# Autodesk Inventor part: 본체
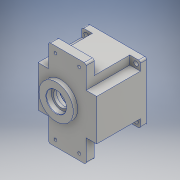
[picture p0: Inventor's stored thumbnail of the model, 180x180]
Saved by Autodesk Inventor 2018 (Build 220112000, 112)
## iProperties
Created: 2020-07
Part Number: 본체
Material: 알루미늄 6061
Document SubType Name: Modeling
Designer: Admin
Density: 2.7 g/cm^3
Appearance: 알루미늄 - 평지
Mass: 876.465 g
Surface Area: 793.597 cm^2
Volume: 324.617 cm^3
Author: Admin
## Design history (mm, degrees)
sketch "스케치1"
  geometry: L1 (-30, 70)-(30, 70); L2 (30, 70)-(30, -70); L3 (30, -70)-(-30, -70); L4 (-30, -70)-(-30, 70); L5 (-30, 70)-(30, -70); L6 (30, 70)-(-30, -70); 1 further point
  constraints: 12 end point, 2 midpoint, 2 parallel, 1 horizontal, 1 perpendicular
  dimensions: "d0" = 140 distance of L1.end L2.end; "d1" = 60 distance between parallel lines of L4 L2
extrude "돌출1" new body sketch "스케치1" distance "d2" = 13; taper "d3" = 0 deg
sketch "스케치2"
  geometry: L1 (-47, 47)-(47, 47); L2 (47, 47)-(47, -47); L3 (47, -47)-(-47, -47); L4 (-47, -47)-(-47, 47); L5 (-47, 47)-(47, -47); L6 (47, 47)-(-47, -47); 1 further point
  constraints: 12 end point, 2 midpoint, 2 parallel, 1 horizontal, 1 perpendicular
  dimensions: "d4" = 94 distance of L1.end L2.end; "d5" = 94 distance of L2.end L3.end
extrude "돌출2" join sketch "스케치2" distance "d6" = 80; taper "d7" = 0 deg
sketch "스케치3"
  geometry: L1 (-30, 33)-(30, 33); L2 (30, 33)-(30, -33); L3 (30, -33)-(-30, -33); L4 (-30, -33)-(-30, 33); L5 (-30, 33)-(30, -33); L6 (30, 33)-(-30, -33); L7 (47, 47)-(47, -47) reference; L8 (30, -33)-(47, -33); L9 (47, -33)-(47, -47); L10 (47, -47)-(30, -47); L11 (30, -47)-(30, -33); L12 (30, 33)-(47, 33); L13 (47, 33)-(47, 47); L14 (47, 47)-(30, 47); L15 (30, 47)-(30, 33); L16 (-47, 47)-(-30, 47) reference; L17 (-30, 33)-(-47, 33); L18 (-47, 33)-(-47, 47); L19 (-47, 47)-(-30, 47); L20 (-30, 47)-(-30, 33); L21 (-47, -47)-(-47, 47) reference; L22 (-30, -33)-(-47, -33); L23 (-47, -33)-(-47, -47); L24 (-47, -47)-(-30, -47); L25 (-30, -47)-(-30, -33); 1 further point
  constraints: 44 end point, 10 parallel, 5 horizontal, 5 perpendicular, 2 midpoint
  dimensions: "d8" = 66 distance of L1.end L2.end; "d9" = 60 distance of L2.end L3.end
extrude "돌출3" cut sketch "스케치3" distance "d10" = 70; taper "d11" = 0 deg
sketch "스케치4"
  geometry: C1 r 43 at (0, 0); 1 further point
  constraints: 1 centre point, 1 coincident
  dimensions: "d12" = 86 diameter of C1
extrude "돌출4" cut sketch "스케치4" distance "d13" = 9; taper "d14" = 0 deg
sketch "스케치5"
  geometry: C1 r 40 at (0, 0); 1 further point
  constraints: 1 centre point, 1 coincident
  dimensions: "d15" = 80 diameter of C1
extrude "돌출5" cut sketch "스케치5" distance "d16" = 62; taper "d17" = 0 deg
sketch "스케치6"
  geometry: L1 (0, -40)-(0, 40); L2 (-40, 0)-(40, 0); L3 (-11, -40)-(-11, 40); L4 (20, -40)-(20, 40); A1 r 40 centre (0, 0) between (0, -40) and (0, 40) reference; A2 r 21 centre (-11, 0) between (6.119, 12.163) and (6.119, -12.163); A3 r 15 centre (20, 0) between (10.47, -11.584) and (10.47, 11.584); A4 r 3 centre (8.565, -13.901) between (10.47, -11.584) and (6.119, -12.163); A5 r 3 centre (8.565, 13.901) between (6.119, 12.163) and (10.47, 11.584); 3 further points
  constraints: 12 point on circle, 8 end point, 6 midpoint, 4 centre point, 3 symmetric about line, 2 parallel, 2 point on line, 2 tangent, 1 horizontal, 1 vertical, 1 other
  dimensions: "d18" = 11 distance between parallel lines of L1 L3; "d19" = 20 distance between parallel lines of L1 L4; "d20" = 42 diameter of A2; "d21" = 30 diameter of A3; "d22" = 6 diameter of A4
extrude "돌출6" join sketch "스케치6" distance "d23" = 7; taper "d24" = 0 deg
sketch "스케치7"
  geometry: C1 r 17.5 at (-11, 0); A1 r 21 centre (-11, 0) between (6.119, 12.163) and (6.119, -12.163) reference; 1 further point
  constraints: 1 centre point, 1 coincident
  dimensions: "d25" = 35 diameter of C1
extrude "돌출7" cut sketch "스케치7" distance "d26" = 10; taper "d27" = 0 deg
sketch "스케치8"
  geometry: C1 r 27.5 at (-11, 0); A1 r 21 centre (-11, 0) between (6.119, 12.163) and (6.119, -12.163) reference; 1 further point
  constraints: 1 centre point, 1 coincident
  dimensions: "d28" = 55 diameter of C1
extrude "돌출8" join sketch "스케치8" distance "d29" = 7; taper "d30" = 0 deg
sketch "스케치9"
  geometry: C1 r 27.5 at (0, 0) reference; C2 r 16 at (0, 0); 1 further point
  constraints: 1 centre point, 1 coincident
  dimensions: "d31" = 32 diameter of C2
extrude "돌출9" cut sketch "스케치9" distance "d32" = 8.3; taper "d33" = 0 deg
sketch "스케치10"
  geometry: C1 r 27.5 at (0, 0) reference; C2 r 12.5 at (0, 0); 1 further point
  constraints: 1 centre point, 1 coincident
  dimensions: "d34" = 25 diameter of C2
extrude "돌출10" cut sketch "스케치10" extent not by distance; stored distance "d35" = 8.3; taper "d36" = 0 deg
sketch "스케치11"
  geometry: C1 r 11 at (20, 0); A1 r 15 centre (20, 0) between (10.47, -11.584) and (10.47, 11.584) reference; 1 further point
  constraints: 1 centre point, 1 coincident
  dimensions: "d37" = 22 diameter of C1
extrude "돌출11" cut sketch "스케치11" distance "d38" = 7; taper "d39" = 0 deg
sketch "스케치12"
  geometry: C1 r 11 at (0, 0) reference; C2 r 9.5 at (0, 0); 1 further point
  constraints: 1 centre point, 1 coincident
  dimensions: "d40" = 19 diameter of C2
extrude "돌출12" cut sketch "스케치12" distance "d41" = 3; taper "d42" = 0 deg
sketch "스케치13"
  geometry: L1 (40, 40)-(-40, 40); L2 (-40, 40)-(-40, -40); L3 (-40, -40)-(40, -40); L4 (40, -40)-(40, 40); L5 (40, 40)-(-40, -40); L6 (-40, 40)-(40, -40); C1 r 3.5 at (40, -40); C2 r 3.5 at (-40, -40); C3 r 3.5 at (-40, 40); C4 r 3.5 at (40, 40); 2 further points
  constraints: 12 end point, 5 coincident, 4 centre point, 2 midpoint, 2 parallel, 1 horizontal, 1 perpendicular
  dimensions: "d43" = 80 distance of L2.end L3.end; "d44" = 80 distance of L1.end L2.end; "d45" = 7 diameter of C1; "d46" = 7 diameter of C2; "d47" = 7 diameter of C3; "d48" = 7 diameter of C4
extrude "돌출13" cut sketch "스케치13" extent not by distance; stored distance "d49" = 3; taper "d50" = 0 deg
sketch "스케치14"
  geometry: L1 (19, -60)-(-19, -60); L2 (-19, -60)-(-19, 60); L3 (-19, 60)-(19, 60); L4 (19, 60)-(19, -60); L5 (19, -60)-(-19, 60); L6 (-19, -60)-(19, 60); 5 further points
  constraints: 12 end point, 4 coincident, 2 midpoint, 2 parallel, 1 horizontal, 1 perpendicular
  dimensions: "d51" = 120 distance of L1.end L2.end; "d52" = 38 distance of L1.start L1.end
hole "구멍1" sketch "스케치14" at (-19, -60), (19, -60), (-19, 60), (19, 60) diameter "d53" = 4.5; stored, may be unused: countersink angle "d57" = 90 deg, drill point angle "d59" = 0 deg; dims "d54" = 6, "d55" = 10, "d56" = 5, "d58" = 8
sketch "스케치15"
  geometry: L1 (0, -36)-(0, 36); L2 (-36, 0)-(36, 0); A1 r 36 centre (0, 0) between (0, -36) and (0, 36); A2 r 4 centre (0, -36) between (3.995, -36.19) and (-3.995, -36.19); A3 r 4 centre (0, 36) between (-3.995, 36.19) and (3.995, 36.19); A4 r 3 centre (-6.992, -36.333) between (-7.559, -39.279) and (-4.045, -35.772); A5 r 3 centre (6.992, -36.333) between (4.045, -35.772) and (7.559, -39.279); A6 r 3 centre (-6.992, 36.333) between (-4.045, 35.772) and (-7.559, 39.279); A7 r 3 centre (6.992, 36.333) between (7.559, 39.279) and (4.045, 35.772); A8 r 40 centre (0, 0) between (-7.559, -39.279) and (7.559, -39.279); A9 r 40 centre (0, 0) between (7.559, 39.279) and (-7.559, 39.279); 4 further points
  constraints: 25 point on circle, 9 centre point, 9 symmetric about line, 5 coincident, 4 end point, 4 midpoint, 1 horizontal, 1 tangent, 1 vertical, 6 other
  dimensions: "d60" = 72 diameter of A1; "d61" = 8 diameter of A2; "d62" = 8 diameter of A3; "d63" = 6 diameter of A4
extrude "돌출14" join sketch "스케치15" stored distance "d64" = 3; taper "d65" = 0 deg
sketch "스케치16"
  geometry: A1 r 4 centre (0, -36) between (3.995, -36.19) and (-3.995, -36.19) reference; A2 r 4 centre (0, 36) between (-3.995, 36.19) and (3.995, 36.19) reference; 3 further points
  constraints: 2 coincident
hole "구멍2" sketch "스케치16" at (0, -36), (0, 36) diameter "d66" = 3.242; stored, may be unused: countersink angle "d70" = 90 deg, drill point angle "d72" = 118 deg; dims "d67" = 7, "d68" = 10, "d69" = 5, "d71" = 9
chamfer "모따기1" distance "d73" = 0.8; stored, may be unused: second distance "d74" = 2, angle "d75" = 30 deg
fillet "모깎기1" dims "d76" = 3
chamfer "모따기2" distance "d77" = 1; stored, may be unused: second distance "d78" = 2, angle "d79" = 45 deg
chamfer "모따기3" distance "d80" = 1; stored, may be unused: second distance "d81" = 2, angle "d82" = 45 deg
fillet "모깎기2" dims "d83" = 3
fillet "모깎기3" dims "d84" = 3
sketch "스케치17"
  geometry: L1 (-11, 80)-(77, 80) reference; L2 (77, 80)-(-11, 80) reference; L3 (33, 0)-(33, 80); 2 further points
  constraints: 2 end point, 2 midpoint, 1 coincident, 1 other
  dimensions: "d90" = 40 distance from line of L1 point (33, 40)
feature "엠보싱1" sketch "스케치17" dims "d0" = 140, "d1" = 60, "d8" = 66, "d9" = 60, "d87" = 0.5, "d88" = 0
chamfer "모따기4" distance "d91" = 1; stored, may be unused: second distance "d92" = 2, angle "d93" = 45 deg
node "솔리드1"
